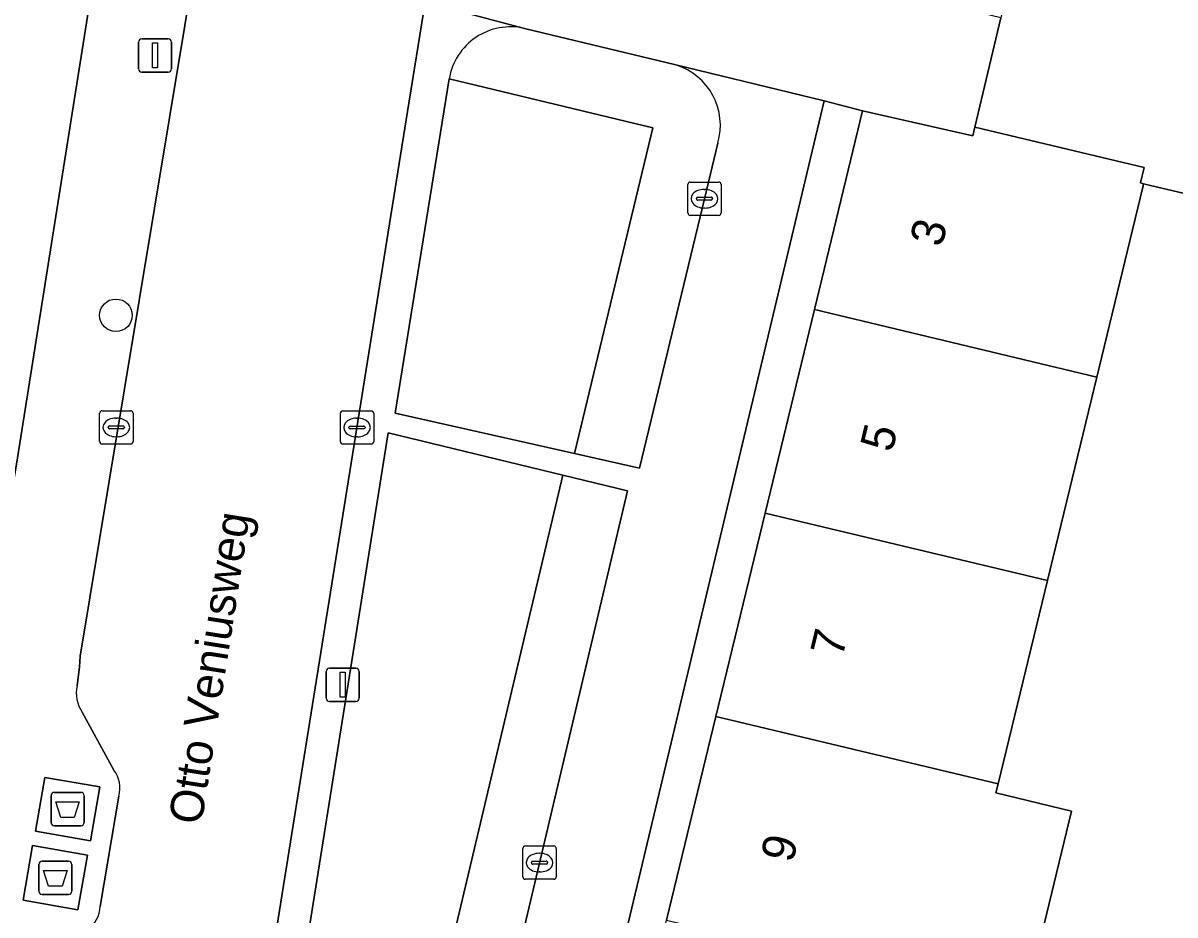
# Model space of a CAD drawing. Extents: x 162803 to 163818, y 381639 to 382475.
# Drawn here: x 163109.85 to 163144.42, y 382389.19 to 382415.94 of the extents above; entities that cross this region are included whole.
import ezdxf

# ---------------------------------------------------------------- set-up
doc = ezdxf.new("R2010")
doc.units = 0
for name, color, linetype in [('IMGEO_Afval_apart_plaats', 7, 'Continuous'), ('IMGEO_Boom', 7, 'Continuous'), ('IMGEO_Erf', 7, 'Continuous'), ('IMGEO_Groenvoorziening', 7, 'Continuous'), ('IMGEO_Kolk', 7, 'Continuous'), ('IMGEO_Lichtmast', 7, 'Continuous'), ('IMGEO_Openbare_ruimte_label', 7, 'Continuous'), ('IMGEO_Pand', 7, 'Continuous'), ('IMGEO_Pand_nummerreeks', 7, 'Continuous'), ('IMGEO_Rijbaan_lokaal_gesloten', 7, 'Continuous'), ('IMGEO_Voetpad_gesloten', 7, 'Continuous'), ('IMGEO_Voetpad_open', 7, 'Continuous')]:
    doc.layers.add(name, color=color, linetype=linetype)

msp = doc.modelspace()

# ---------------------------------------------------------------- linework, layer by layer
at = {"layer": 'IMGEO_Afval_apart_plaats'}
for p, q in [((163110.691, 382391.964), (163110.691, 382392.764)), ((163110.691, 382392.764), (163110.691, 382391.964)), ((163110.791, 382392.864), (163111.581, 382392.864)), ((163111.581, 382392.864), (163110.791, 382392.864)), ((163111.681, 382392.764), (163111.681, 382391.964)), ((163111.681, 382391.964), (163111.681, 382392.764)), ((163111.581, 382391.864), (163110.791, 382391.864)), ((163110.791, 382391.864), (163111.581, 382391.864)), ((163110.323, 382389.902), (163110.323, 382390.702)), ((163110.323, 382390.702), (163110.323, 382389.902)), ((163110.423, 382390.802), (163111.213, 382390.802)), ((163111.213, 382390.802), (163110.423, 382390.802)), ((163111.313, 382390.702), (163111.313, 382389.902)), ((163111.313, 382389.902), (163111.313, 382390.702)), ((163111.213, 382389.802), (163110.423, 382389.802)), ((163110.423, 382389.802), (163111.213, 382389.802))]:
    msp.add_line(p, q, dxfattribs=at)
for points in [[(163110.834, 382392.578), (163111.538, 382392.578), (163111.389, 382392.108), (163110.983, 382392.108), (163110.834, 382392.578)], [(163110.466, 382390.516), (163111.17, 382390.516), (163111.021, 382390.046), (163110.615, 382390.046), (163110.466, 382390.516)]]:
    msp.add_lwpolyline(points, dxfattribs=at)
for centre, start, end in [((163110.791, 382392.764), 90, 180), ((163110.791, 382392.764), 90, 180), ((163111.581, 382392.764), 0, 90), ((163111.581, 382392.764), 360, 90), ((163110.791, 382391.964), 180, 270), ((163110.791, 382391.964), 180, 270), ((163111.581, 382391.964), 270, 0), ((163111.581, 382391.964), 270, 0), ((163110.423, 382390.702), 90, 180), ((163110.423, 382390.702), 90, 180), ((163111.213, 382390.702), 0, 90), ((163111.213, 382390.702), 360, 90), ((163110.423, 382389.902), 180, 270), ((163110.423, 382389.902), 180, 270), ((163111.213, 382389.902), 270, 0), ((163111.213, 382389.902), 270, 0)]:
    msp.add_arc(centre, 0.1, start, end, dxfattribs=at)
at = {"layer": 'IMGEO_Boom'}
msp.add_circle((163112.637, 382407.176), 0.489, dxfattribs=at)
at = {"layer": 'IMGEO_Erf'}
for points in [[(163108.694, 382396.964), (163109.688, 382402.897), (163112.543, 382420.938), (163112.75, 382422.426), (163113.395, 382426.511), (163102.776, 382429.01), (163081.558, 382434.002), (163076.134, 382435.357), (163059.186, 382439.194), (163058.429, 382438.955), (163057.549, 382434.766), (163057.269, 382434.813), (163056.547, 382430.876), (163056.692, 382430.848), (163056.668, 382430.717), (163055.342, 382426.312), (163054.592, 382422.204), (163054.372, 382422.252), (163052.737, 382414.344), (163051.991, 382410.736), (163051.66, 382410.862), (163048.783, 382397.461)], [(163146.067, 382410.506), (163143.482, 382411.123), (163143.457, 382411.02), (163142.076, 382405.325), (163140.596, 382399.221), (163139.116, 382393.116), (163139.052, 382392.854), (163141.321, 382392.304), (163139.907, 382386.469), (163137.636, 382387.011), (163136.051, 382380.474), (163127.586, 382382.526), (163129.164, 382389.034), (163130.644, 382395.139), (163132.124, 382401.244), (163133.604, 382407.349), (163135.05, 382413.314), (163133.892, 382413.61), (163126.539, 382382.771), (163126.023, 382380.609), (163144.89, 382376.049)]]:
    msp.add_lwpolyline(points, dxfattribs=at)
at = {"layer": 'IMGEO_Groenvoorziening'}
for points in [[(163129.439, 382414.69), (163124.899, 382415.784)], [(163122.641, 382414.27), (163128.757, 382412.797), (163126.402, 382403.029), (163128.353, 382402.59), (163130.31, 382410.706), (163130.7, 382412.34)], [(163124.076, 382385.368), (163127.996, 382401.907), (163126.053, 382402.379), (163122.14, 382385.87), (163118.132, 382386.827), (163117.966, 382385.784)]]:
    msp.add_lwpolyline(points, dxfattribs=at)
for points in [[(163128.757, 382412.797), (163122.641, 382414.27), (163121.018, 382404.24), (163126.402, 382403.029)], [(163118.132, 382386.827), (163122.14, 382385.87), (163126.053, 382402.379), (163120.807, 382403.654)]]:
    msp.add_lwpolyline(points, close=True, dxfattribs=at)
for centre, radius, start, end in [((163124.484, 382413.963), 1.868, 77.1573, 170.5268), ((163128.887, 382412.88), 1.892, 343.4005, 73.0352)]:
    msp.add_arc(centre, radius, start, end, dxfattribs=at)
at = {"layer": 'IMGEO_Kolk'}
for p, q in [((163129.802, 382410.248), (163129.802, 382411.1)), ((163129.877, 382411.174), (163130.729, 382411.174)), ((163130.29, 382410.954), (163130.315, 382410.954)), ((163130.803, 382411.1), (163130.803, 382410.248)), ((163130.061, 382410.668), (163130.061, 382410.68)), ((163130.499, 382410.631), (163130.101, 382410.631)), ((163130.104, 382410.717), (163130.502, 382410.717)), ((163130.545, 382410.68), (163130.545, 382410.668)), ((163130.313, 382410.394), (163130.288, 382410.394)), ((163130.729, 382410.174), (163129.877, 382410.174)), ((163112.225, 382404.313), (163113.077, 382404.313)), ((163112.15, 382403.387), (163112.15, 382404.239)), ((163112.638, 382404.093), (163112.663, 382404.093)), ((163113.151, 382404.239), (163113.151, 382403.387)), ((163119.374, 382403.384), (163119.374, 382404.236)), ((163119.449, 382404.31), (163120.301, 382404.31)), ((163119.862, 382404.09), (163119.887, 382404.09)), ((163120.375, 382404.236), (163120.375, 382403.384)), ((163112.409, 382403.807), (163112.409, 382403.819)), ((163112.847, 382403.77), (163112.449, 382403.77)), ((163112.452, 382403.856), (163112.85, 382403.856)), ((163112.893, 382403.819), (163112.893, 382403.807)), ((163119.633, 382403.804), (163119.633, 382403.816)), ((163120.071, 382403.767), (163119.673, 382403.767)), ((163119.676, 382403.853), (163120.074, 382403.853)), ((163120.117, 382403.816), (163120.117, 382403.804)), ((163113.077, 382403.313), (163112.225, 382403.313)), ((163112.661, 382403.533), (163112.636, 382403.533)), ((163120.301, 382403.31), (163119.449, 382403.31)), ((163119.885, 382403.53), (163119.86, 382403.53)), ((163124.853, 382390.329), (163124.853, 382391.181)), ((163124.928, 382391.255), (163125.78, 382391.255)), ((163125.854, 382391.181), (163125.854, 382390.329)), ((163125.341, 382391.035), (163125.366, 382391.035)), ((163125.112, 382390.749), (163125.112, 382390.761)), ((163125.55, 382390.712), (163125.152, 382390.712)), ((163125.155, 382390.798), (163125.553, 382390.798)), ((163125.596, 382390.761), (163125.596, 382390.749)), ((163125.78, 382390.255), (163124.928, 382390.255)), ((163125.364, 382390.475), (163125.339, 382390.475))]:
    msp.add_line(p, q, dxfattribs=at)
for points in [[(163129.802, 382410.248), (163129.802, 382411.1)], [(163129.877, 382411.174), (163130.729, 382411.174)], [(163130.803, 382411.1), (163130.803, 382410.248)], [(163130.729, 382410.174), (163129.877, 382410.174)], [(163112.225, 382404.313), (163113.077, 382404.313)], [(163112.15, 382403.387), (163112.15, 382404.239)], [(163113.151, 382404.239), (163113.151, 382403.387)], [(163119.374, 382403.384), (163119.374, 382404.236)], [(163119.449, 382404.31), (163120.301, 382404.31)], [(163120.375, 382404.236), (163120.375, 382403.384)], [(163113.077, 382403.313), (163112.225, 382403.313)], [(163120.301, 382403.31), (163119.449, 382403.31)], [(163124.853, 382390.329), (163124.853, 382391.181)], [(163124.928, 382391.255), (163125.78, 382391.255)], [(163125.854, 382391.181), (163125.854, 382390.329)], [(163125.78, 382390.255), (163124.928, 382390.255)]]:
    msp.add_lwpolyline(points, dxfattribs=at)
for centre, radius, start, end in [((163129.879, 382411.098), 0.0765, 91.552, 178.448), ((163129.879, 382411.098), 0.0765, 91.552, 178.448), ((163130.727, 382411.098), 0.0765, 1.552, 88.448), ((163130.727, 382411.098), 0.0765, 1.552, 88.448), ((163130.101, 382410.677), 0.0403, 85.8775, 175.7526), ((163130.098, 382410.667), 0.0366, 178.938, 274.7102), ((163130.502, 382410.674), 0.043, 264.8664, 352.4533), ((163130.506, 382410.679), 0.0386, 1.7309, 96.639), ((163129.879, 382410.25), 0.0765, 181.552, 268.448), ((163129.879, 382410.25), 0.0765, 181.552, 268.448), ((163130.727, 382410.25), 0.0765, 271.552, 358.448), ((163130.727, 382410.25), 0.0765, 271.552, 358.448), ((163112.227, 382404.237), 0.0765, 91.552, 178.448), ((163112.227, 382404.237), 0.0765, 91.552, 178.448), ((163113.075, 382404.237), 0.0765, 1.552, 88.448), ((163113.075, 382404.237), 0.0765, 1.552, 88.448), ((163119.451, 382404.234), 0.0765, 91.552, 178.448), ((163119.451, 382404.234), 0.0765, 91.552, 178.448), ((163120.299, 382404.234), 0.0765, 1.552, 88.448), ((163120.299, 382404.234), 0.0765, 1.552, 88.448), ((163112.449, 382403.816), 0.0403, 85.8775, 175.7526), ((163112.446, 382403.806), 0.0366, 178.938, 274.7102), ((163112.85, 382403.813), 0.043, 264.8664, 352.4533), ((163112.854, 382403.818), 0.0386, 1.7309, 96.639), ((163119.673, 382403.813), 0.0403, 85.8775, 175.7526), ((163119.67, 382403.803), 0.0366, 178.938, 274.7102), ((163120.074, 382403.81), 0.043, 264.8664, 352.4533), ((163120.078, 382403.815), 0.0386, 1.7309, 96.639), ((163112.227, 382403.389), 0.0765, 181.552, 268.448), ((163112.227, 382403.389), 0.0765, 181.552, 268.448), ((163113.075, 382403.389), 0.0765, 271.552, 358.448), ((163113.075, 382403.389), 0.0765, 271.552, 358.448), ((163119.451, 382403.386), 0.0765, 181.552, 268.448), ((163119.451, 382403.386), 0.0765, 181.552, 268.448), ((163120.299, 382403.386), 0.0765, 271.552, 358.448), ((163120.299, 382403.386), 0.0765, 271.552, 358.448), ((163124.93, 382391.179), 0.0765, 91.552, 178.448), ((163124.93, 382391.179), 0.0765, 91.552, 178.448), ((163125.778, 382391.179), 0.0765, 1.552, 88.448), ((163125.778, 382391.179), 0.0765, 1.552, 88.448), ((163125.152, 382390.758), 0.0403, 85.8775, 175.7526), ((163125.149, 382390.748), 0.0366, 178.938, 274.7102), ((163125.553, 382390.755), 0.043, 264.8664, 352.4533), ((163125.557, 382390.76), 0.0386, 1.7309, 96.639), ((163124.93, 382390.331), 0.0765, 181.552, 268.448), ((163124.93, 382390.331), 0.0765, 181.552, 268.448), ((163125.778, 382390.331), 0.0765, 271.552, 358.448), ((163125.778, 382390.331), 0.0765, 271.552, 358.448)]:
    msp.add_arc(centre, radius, start, end, dxfattribs=at)
for centre, major_axis, ratio, start_param, end_param in [((163130.289, 382410.674), (-0.387, 0.002), 0.722429, 4.712389, 7.853982), ((163130.314, 382410.674), (-0.39, 0.002), 0.717154, 1.570796, 4.712389), ((163112.637, 382403.813), (-0.387, 0.002), 0.722429, 4.712389, 7.853982), ((163112.662, 382403.813), (-0.39, 0.002), 0.717154, 1.570796, 4.712389), ((163119.861, 382403.81), (-0.387, 0.002), 0.722429, 4.712389, 7.853982), ((163119.886, 382403.81), (-0.39, 0.002), 0.717154, 1.570796, 4.712389), ((163125.34, 382390.755), (-0.387, 0.002), 0.722429, 4.712389, 7.853982), ((163125.365, 382390.755), (-0.39, 0.002), 0.717154, 1.570796, 4.712389)]:
    msp.add_ellipse(centre, major_axis=major_axis, ratio=ratio, start_param=start_param, end_param=end_param, dxfattribs=at)
at = {"layer": 'IMGEO_Lichtmast'}
for p, q in [((163113.418, 382415.473), (163114.208, 382415.473)), ((163114.208, 382415.473), (163113.418, 382415.473)), ((163113.318, 382414.573), (163113.318, 382415.373)), ((163113.318, 382415.373), (163113.318, 382414.573)), ((163114.308, 382415.373), (163114.308, 382414.573)), ((163114.308, 382414.573), (163114.308, 382415.373)), ((163114.208, 382414.473), (163113.418, 382414.473)), ((163113.418, 382414.473), (163114.208, 382414.473)), ((163118.948, 382395.691), (163118.948, 382396.491)), ((163118.948, 382396.491), (163118.948, 382395.691)), ((163119.048, 382396.591), (163119.838, 382396.591)), ((163119.838, 382396.591), (163119.048, 382396.591)), ((163119.938, 382396.491), (163119.938, 382395.691)), ((163119.938, 382395.691), (163119.938, 382396.491)), ((163119.838, 382395.591), (163119.048, 382395.591)), ((163119.048, 382395.591), (163119.838, 382395.591))]:
    msp.add_line(p, q, dxfattribs=at)
for points in [[(163113.738, 382415.348), (163113.888, 382415.348), (163113.888, 382414.598), (163113.738, 382414.598), (163113.738, 382415.348)], [(163119.368, 382396.466), (163119.518, 382396.466), (163119.518, 382395.716), (163119.368, 382395.716), (163119.368, 382396.466)]]:
    msp.add_lwpolyline(points, dxfattribs=at)
for centre, start, end in [((163113.418, 382415.373), 90, 180), ((163113.418, 382415.373), 90, 180), ((163114.208, 382415.373), 0, 90), ((163114.208, 382415.373), 360, 90), ((163113.418, 382414.573), 180, 270), ((163113.418, 382414.573), 180, 270), ((163114.208, 382414.573), 270, 0), ((163114.208, 382414.573), 270, 0), ((163119.048, 382396.491), 90, 180), ((163119.048, 382396.491), 90, 180), ((163119.838, 382396.491), 0, 90), ((163119.838, 382396.491), 360, 90), ((163119.048, 382395.691), 180, 270), ((163119.048, 382395.691), 180, 270), ((163119.838, 382395.691), 270, 0), ((163119.838, 382395.691), 270, 0)]:
    msp.add_arc(centre, 0.1, start, end, dxfattribs=at)
at = {"layer": 'IMGEO_Pand'}
for points in [[(163149.329, 382420.611), (163140.776, 382422.692), (163139.203, 382416.099), (163138.42, 382412.816), (163143.496, 382411.608), (163143.386, 382411.146), (163143.482, 382411.123), (163146.067, 382410.506), (163146.859, 382413.824), (163147.662, 382413.632)], [(163143.457, 382411.02), (163143.482, 382411.123), (163143.386, 382411.146), (163143.496, 382411.608), (163138.42, 382412.816), (163138.358, 382412.558), (163135.05, 382413.314), (163133.604, 382407.349), (163142.076, 382405.325)], [(163142.076, 382405.325), (163133.604, 382407.349), (163132.124, 382401.244), (163140.596, 382399.221)], [(163132.124, 382401.244), (163130.644, 382395.139), (163139.116, 382393.116), (163140.596, 382399.221)], [(163141.321, 382392.304), (163139.052, 382392.854), (163139.116, 382393.116), (163130.644, 382395.139), (163129.164, 382389.034), (163137.636, 382387.011), (163139.907, 382386.469)]]:
    msp.add_lwpolyline(points, close=True, dxfattribs=at)
at = {"layer": 'IMGEO_Rijbaan_lokaal_gesloten'}
for points in [[(163116.054, 382424.247), (163115.16, 382418.587), (163112.435, 382402.2), (163111.562, 382396.95), (163111.548, 382396.631), (163111.476, 382396.063)], [(163121.392, 382413.294), (163121.918, 382416.569), (163122.437, 382420.146), (163122.916, 382422.786)], [(163113.128, 382361.839), (163114.269, 382369.06), (163116.931, 382385.451), (163121.392, 382413.294)], [(163111.628, 382395.272), (163112.575, 382393.532)], [(163112.727, 382392.75), (163112.169, 382389.443)]]:
    msp.add_lwpolyline(points, dxfattribs=at)
for centre, radius, start, end in [((163112.408, 382395.832), 0.96, 166.0766, 215.6784), ((163111.875, 382392.99), 0.885, 344.245, 37.7542), ((163111.277, 382389.482), 0.893, 304.5295, 357.5149)]:
    msp.add_arc(centre, radius, start, end, dxfattribs=at)
at = {"layer": 'IMGEO_Voetpad_gesloten'}
for points in [[(163112.151, 382393.026), (163110.502, 382393.313), (163110.221, 382391.701), (163111.87, 382391.414)], [(163111.784, 382390.977), (163110.139, 382391.266), (163109.851, 382389.626), (163111.496, 382389.337)]]:
    msp.add_lwpolyline(points, close=True, dxfattribs=at)
at = {"layer": 'IMGEO_Voetpad_open'}
for points in [[(163116.24, 382425.96), (163113.395, 382426.511), (163112.75, 382422.426), (163112.543, 382420.938), (163109.688, 382402.897), (163108.694, 382396.964), (163103.117, 382362.845)], [(163111.476, 382396.063), (163111.548, 382396.631), (163111.562, 382396.95), (163112.435, 382402.2), (163115.16, 382418.587), (163116.054, 382424.247)], [(163124.899, 382415.784), (163121.918, 382416.569), (163121.392, 382413.294), (163116.931, 382385.451)], [(163133.892, 382413.61), (163129.439, 382414.69)], [(163130.7, 382412.34), (163130.31, 382410.706), (163128.353, 382402.59), (163126.402, 382403.029), (163121.018, 382404.24), (163122.641, 382414.27)], [(163121.862, 382383.88), (163126.539, 382382.771), (163133.892, 382413.61)], [(163117.966, 382385.784), (163118.132, 382386.827), (163120.807, 382403.654), (163126.053, 382402.379), (163127.996, 382401.907), (163124.076, 382385.368)], [(163112.575, 382393.532), (163111.628, 382395.272)], [(163112.169, 382389.443), (163112.727, 382392.75)]]:
    msp.add_lwpolyline(points, dxfattribs=at)
for points in [[(163139.203, 382416.099), (163122.437, 382420.146), (163121.918, 382416.569), (163124.899, 382415.784), (163129.439, 382414.69), (163133.892, 382413.61), (163135.05, 382413.314), (163138.358, 382412.558), (163138.42, 382412.816)], [(163110.502, 382393.313), (163112.151, 382393.026), (163111.87, 382391.414), (163110.221, 382391.701)], [(163111.784, 382390.977), (163111.496, 382389.337), (163109.851, 382389.626), (163110.139, 382391.266)]]:
    msp.add_lwpolyline(points, close=True, dxfattribs=at)
for centre, radius, start, end in [((163124.484, 382413.963), 1.868, 77.1573, 170.5268), ((163128.887, 382412.88), 1.892, 343.4005, 73.0352), ((163112.408, 382395.832), 0.96, 166.0766, 215.6784), ((163111.875, 382392.99), 0.885, 344.245, 37.7542), ((163111.277, 382389.482), 0.893, 304.5295, 357.5149)]:
    msp.add_arc(centre, radius, start, end, dxfattribs=at)

# ---------------------------------------------------------------- texts
at = {"layer": 'IMGEO_Openbare_ruimte_label'}
msp.add_text('Otto Veniusweg', height=1, rotation=81.084, dxfattribs=at).set_placement((163115.203, 382391.863))
at = {"layer": 'IMGEO_Pand_nummerreeks'}
for s, rotation, p in [('3', 76.3753, (163137.426, 382409.194)), ('5', 76.3726, (163135.933, 382403.036)), ('7', 76.3726, (163134.44, 382396.879)), ('9', 76.3753, (163132.948, 382390.721))]:
    msp.add_text(s, height=1, rotation=rotation, dxfattribs=at).set_placement(p)

doc.saveas('drawing.dxf')
